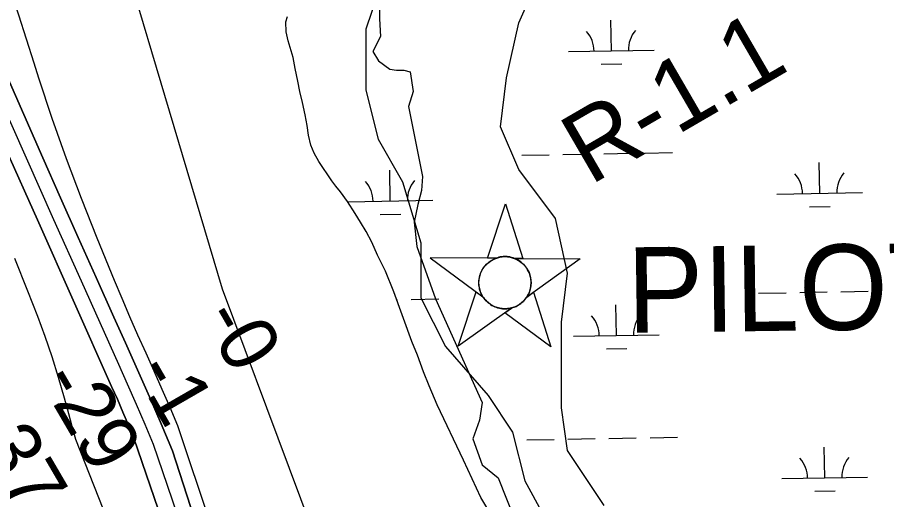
# Model space of a CAD drawing. Extents: x 3914892 to 3953151, y 242587 to 268572.
# Drawn here: x 3943744 to 3944760, y 249840 to 250403 of the extents above; entities that cross this region are included whole.
import ezdxf

# ---------------------------------------------------------------- set-up
doc = ezdxf.new("R2010")
doc.units = 0
for name, color, linetype in [('V-CHAN-NAID', 7, 'Continuous'), ('V-RIVR-EDGE', 7, 'Continuous'), ('V-RIVR-RANG', 7, 'Continuous'), ('V-RIVR-RANG-IDEN', 7, 'Continuous'), ('V-SITE-VEGE', 7, 'Continuous'), ('V-TOPO-DPTH', 7, 'Continuous'), ('V-TOPO-MINR', 7, 'Continuous'), ('V-TOPO-WATR', 7, 'Continuous'), ('V-WETL-SWMP', 7, 'Continuous')]:
    doc.layers.add(name, color=color, linetype=linetype)

msp = doc.modelspace()

# ---------------------------------------------------------------- linework, layer by layer
at = {"layer": 'V-CHAN-NAID'}
for points in [[(3944302.8, 250121.8), (3944293.3, 250121.8), (3944314.4, 250185.3), (3944334.6, 250121.5), (3944325, 250121.6), (3944323.4, 250122.2), (3944321.4, 250122.8), (3944319.3, 250123.3), (3944317.3, 250123.6), (3944316.1, 250123.7), (3944314.6, 250123.8), (3944312.9, 250123.8), (3944311.5, 250123.7), (3944309.6, 250123.5), (3944308.2, 250123.3), (3944306.4, 250122.9), (3944304.9, 250122.5), (3944303.9, 250122.1)], [(3944302.8, 250121.8), (3944226.4, 250122.3), (3944287.9, 250076.9), (3944286.8, 250078.8), (3944286, 250080.4), (3944285.2, 250082.4), (3944284.5, 250084.5), (3944284.1, 250085.8), (3944283.8, 250087.4), (3944283.5, 250088.9), (3944283.3, 250090.5), (3944283.2, 250092.2), (3944283.2, 250093.8), (3944283.3, 250095.8), (3944283.5, 250097.5), (3944283.9, 250099.7), (3944284.4, 250101.6), (3944285, 250103.5), (3944285.6, 250105.2), (3944286.3, 250106.7), (3944287.2, 250108.3), (3944288.2, 250110), (3944289.3, 250111.5), (3944290.3, 250112.8), (3944291.3, 250113.9), (3944292.6, 250115.2), (3944293.6, 250116.2), (3944295.3, 250117.6), (3944296.5, 250118.5), (3944298.2, 250119.5), (3944300, 250120.5), (3944301.4, 250121.2)], [(3944325, 250121.6), (3944401.5, 250121.1), (3944339.3, 250076.5), (3944340.2, 250078), (3944341.2, 250079.9), (3944341.9, 250081.5), (3944342.7, 250083.4), (3944343.2, 250085.2), (3944343.6, 250086.8), (3944344, 250088.8), (3944344.1, 250090.4), (3944344.3, 250092.6), (3944344.2, 250094.7), (3944344.1, 250096.9), (3944343.8, 250098.7), (3944343.3, 250100.9), (3944342.7, 250103), (3944341.9, 250105), (3944341.3, 250106.5), (3944340.2, 250108.4), (3944339.2, 250110.1), (3944338, 250111.8), (3944336.7, 250113.3), (3944335.4, 250114.7), (3944333.8, 250116.2), (3944332.1, 250117.7), (3944330.4, 250118.8), (3944328.5, 250120), (3944327, 250120.7)], [(3944321.3, 250063.6), (3944259.1, 250019.1), (3944280.2, 250082.6), (3944287.9, 250076.9), (3944288.6, 250075.9), (3944289.9, 250074.1), (3944291.2, 250072.7), (3944292.6, 250071.2), (3944294, 250069.9), (3944295.5, 250068.8), (3944296.9, 250067.8), (3944298.5, 250066.7), (3944300.3, 250065.8), (3944302, 250065), (3944303.5, 250064.5), (3944305.1, 250063.9), (3944307.3, 250063.4), (3944308.9, 250063.1), (3944310.9, 250062.8), (3944312.4, 250062.7), (3944314.3, 250062.7), (3944316, 250062.8), (3944317.7, 250062.9), (3944319.6, 250063.3)], [(3944339.3, 250076.5), (3944347.1, 250082.1), (3944367.3, 250018.3), (3944313.5, 250058.1), (3944321.3, 250063.6), (3944322.9, 250064.1), (3944324.6, 250064.7), (3944326.7, 250065.6), (3944328.5, 250066.5), (3944330.3, 250067.6), (3944332.1, 250068.8), (3944333.6, 250070), (3944334.9, 250071.2), (3944336.3, 250072.6), (3944337.5, 250074), (3944338.6, 250075.5)]]:
    msp.add_lwpolyline(points, close=True, dxfattribs=at)
msp.add_circle((3944313.7, 250093.2), 30.5, dxfattribs=at)
at = {"layer": 'V-RIVR-EDGE'}
msp.add_lwpolyline([(3944167.1, 250418.2), (3944167.1, 250401.8), (3944168.2, 250381.1), (3944159.5, 250363.6), (3944166, 250352.7), (3944179.1, 250342.9), (3944186.8, 250341.8), (3944195.5, 250341.8), (3944203.1, 250339.6), (3944206.4, 250316.7), (3944200.9, 250299.3), (3944217.3, 250217.4), (3944216.2, 250201.1), (3944211.8, 250184.7), (3944207.5, 250164), (3944210.8, 250135.6), (3944232.6, 250074.5), (3944287.1, 249953.4), (3944283.8, 249932.7), (3944276.2, 249910.9), (3944287.1, 249880.3), (3944305.7, 249865.1), (3944325.3, 249816)], dxfattribs=at)
at = {"layer": 'V-SITE-VEGE'}
for points in [[(3944429.7, 249832.9), (3944386.9, 249897.2), (3944379.7, 249947.1), (3944379.7, 250047.1), (3944386.9, 250104.2), (3944372.6, 250168.4), (3944329.8, 250225.5), (3944308.3, 250275.5), (3944315.5, 250332.6), (3944329.8, 250396.9), (3944358.3, 250461.1)], [(3944165.6, 250432.5), (3944151.3, 250389.7), (3944151.3, 250361.2), (3944151.3, 250318.3), (3944165.6, 250261.2), (3944194.1, 250211.3), (3944215.5, 250139.9), (3944215.5, 250075.6), (3944244.1, 250018.5), (3944294.1, 249961.4), (3944322.6, 249918.6), (3944336.9, 249861.5), (3944379.7, 249782.9)]]:
    msp.add_lwpolyline(points, dxfattribs=at)
at = {"layer": 'V-TOPO-DPTH'}
for points in [[(3944620.8, 248476), (3944296.7, 249247.2), (3943983.6, 250085.5), (3943808.9, 250673.8), (3943732.9, 250836.2), (3943663.5, 251001.9), (3943573.7, 251236.8), (3943554.7, 251287.8), (3943536.4, 251339), (3943519.1, 251390.6), (3943502.4, 251442.4), (3943485.5, 251496.3), (3943477.2, 251521.1), (3943468.2, 251545.7), (3943458.2, 251569.8), (3943447.5, 251593.7), (3943436.2, 251617.3), (3943424.7, 251640.8), (3943412.9, 251664.2), (3943401, 251687.5), (3943105.5, 252257.6)], [(3944118.2, 249216.8), (3943880.1, 249911.6), (3943873.7, 249926.8), (3943867.3, 249941.9), (3943860.8, 249957), (3943854.1, 249972), (3943767.3, 250166.8), (3943730.5, 250249.3), (3943693.6, 250331.8), (3943656.6, 250414.3), (3943619.6, 250496.7), (3943563.7, 250621.1), (3943554.6, 250641.4), (3943545.7, 250661.7), (3943536.9, 250682), (3943298.2, 251380.4), (3943287.2, 251406.6), (3943276.1, 251432.8), (3943264.8, 251458.9), (3943253.4, 251485), (3943092.2, 251970.5)], [(3943092.2, 251970.5), (3943253.4, 251485), (3943264.8, 251458.9), (3943276.1, 251432.8), (3943287.2, 251406.6), (3943298.2, 251380.4), (3943536.9, 250682), (3943545.7, 250661.7), (3943554.6, 250641.4), (3943563.7, 250621.1), (3943619.6, 250496.7), (3943656.6, 250414.3), (3943693.6, 250331.8), (3943730.5, 250249.3), (3943767.3, 250166.8), (3943854.1, 249972), (3943860.8, 249957), (3943867.3, 249941.9), (3943873.7, 249926.8), (3943880.1, 249911.6), (3944118.2, 249216.8)], [(3943581.5, 250676.8), (3943773.8, 250239.1), (3943794.4, 250192.5), (3943815.1, 250145.9), (3943835.9, 250099.4), (3943856.7, 250052.9), (3943870.3, 250022.8), (3943884.3, 249991.4), (3943898.2, 249959.9), (3943911.8, 249928.3), (3943925.3, 249896.6), (3944120, 249294.3)], [(3943581.5, 250676.8), (3943773.8, 250239.1), (3943794.4, 250192.5), (3943815.1, 250145.9), (3943835.9, 250099.4), (3943856.7, 250052.9), (3943870.3, 250022.8), (3943884.3, 249991.4), (3943898.2, 249959.9), (3943911.8, 249928.3), (3943925.3, 249896.6), (3944120, 249294.3)], [(3944107.3, 249161.8), (3943812.4, 249910), (3943808, 249925), (3943803.9, 249940.1), (3943799, 249958.4), (3943792.1, 249982.6), (3943784.7, 250006.6), (3943776.4, 250030.3), (3943767.7, 250053.8), (3943756, 250083.5), (3943740.8, 250121.7)], [(3944107.3, 249161.8), (3943812.4, 249910), (3943808, 249925), (3943803.9, 249940.1), (3943799, 249958.4), (3943792.1, 249982.6), (3943784.7, 250006.6), (3943776.4, 250030.3), (3943767.7, 250053.8), (3943756, 250083.5), (3943740.8, 250121.7)]]:
    msp.add_lwpolyline(points, dxfattribs=at)
at = {"layer": 'V-TOPO-MINR'}
for points in [[(3944118.2, 249216.8), (3943880.1, 249911.6), (3943873.7, 249926.8), (3943867.3, 249941.9), (3943860.8, 249957), (3943854.1, 249972), (3943767.3, 250166.8), (3943730.5, 250249.3), (3943693.6, 250331.8), (3943656.6, 250414.3), (3943619.6, 250496.7), (3943563.7, 250621.1), (3943554.6, 250641.4), (3943545.7, 250661.7), (3943536.9, 250682), (3943298.2, 251380.4), (3943287.2, 251406.6), (3943276.1, 251432.8), (3943264.8, 251458.9), (3943253.4, 251485), (3943092.2, 251970.5)], [(3944145.9, 249192), (3943903, 249904), (3943893.1, 249927.5), (3943883, 249951), (3943872.8, 249974.5), (3943862.4, 249997.8), (3943818.8, 250095), (3943786.6, 250166.9), (3943754.5, 250238.8), (3943722.4, 250310.8), (3943690.3, 250382.7), (3943572.2, 250648.2), (3943567.1, 250659.7), (3943562.1, 250671.3), (3943557.2, 250682.9), (3943313.6, 251401), (3943304.7, 251422.7), (3943149, 251911.8)], [(3944120, 249294.3), (3943925.3, 249896.6), (3943911.8, 249928.3), (3943898.2, 249959.9), (3943884.3, 249991.4), (3943870.3, 250022.8), (3943856.7, 250052.9), (3943835.9, 250099.4), (3943815.1, 250145.9), (3943794.4, 250192.5), (3943773.8, 250239.1), (3943581.5, 250676.8)], [(3944165.3, 249227.1), (3943931.5, 249926), (3943922.4, 249947.3), (3943913.2, 249968.5), (3943903.8, 249989.7), (3943894.3, 250010.9), (3943884.9, 250032.1), (3943875.5, 250053.3), (3943866.4, 250074.6), (3943857.5, 250096), (3943837.2, 250145.2), (3943818.9, 250191.5), (3943801.3, 250238), (3943784.8, 250285), (3943769.2, 250332.2), (3943763.6, 250349.9), (3943745.5, 250406.1), (3943727, 250462.2)], [(3944107.3, 249161.8), (3943812.4, 249910), (3943808, 249925), (3943803.9, 249940.1), (3943799, 249958.4), (3943792.1, 249982.6), (3943784.7, 250006.6), (3943776.4, 250030.3), (3943767.7, 250053.8), (3943756, 250083.5), (3943740.8, 250121.7)]]:
    msp.add_lwpolyline(points, dxfattribs=at)
at = {"layer": 'V-TOPO-WATR'}
msp.add_lwpolyline([(3944620.8, 248476), (3944296.7, 249247.2), (3943983.6, 250085.5), (3943808.9, 250673.8), (3943732.9, 250836.2), (3943663.5, 251001.9), (3943573.7, 251236.8), (3943554.7, 251287.8), (3943536.4, 251339), (3943519.1, 251390.6), (3943502.4, 251442.4), (3943485.5, 251496.3), (3943477.2, 251521.1), (3943468.2, 251545.7), (3943458.2, 251569.8), (3943447.5, 251593.7), (3943436.2, 251617.3), (3943424.7, 251640.8), (3943412.9, 251664.2), (3943401, 251687.5), (3943105.5, 252257.6)], dxfattribs=at)
at = {"layer": 'V-WETL-SWMP'}
for p, q in [((3944057.7, 250398.2), (3944059.6, 250404.3)), ((3944438, 250364.2), (3944437.3, 250400.1)), ((3944058.2, 250386.6), (3944057.7, 250398.2)), ((3944060.5, 250376.1), (3944058.2, 250386.6)), ((3944063.9, 250364.4), (3944060.5, 250376.1)), ((3944066.3, 250356.3), (3944063.9, 250364.4)), ((3944388, 250363.3), (3944488, 250365)), ((3944068.4, 250343.7), (3944066.3, 250356.3)), ((3944426.3, 250348.5), (3944450.3, 250348.9)), ((3944071.5, 250328.9), (3944068.4, 250343.7)), ((3944074.1, 250316.9), (3944071.5, 250328.9)), ((3944077.2, 250303.9), (3944074.1, 250316.9)), ((3944080.1, 250289.5), (3944077.2, 250303.9)), ((3944082.4, 250277.1), (3944080.1, 250289.5)), ((3944084.2, 250265.7), (3944082.4, 250277.1)), ((3944086.8, 250254.2), (3944084.2, 250265.7)), ((3944090.7, 250244.5), (3944086.8, 250254.2)), ((3944096.4, 250234.8), (3944090.7, 250244.5)), ((3944333.3, 250242.2), (3944365.3, 250242.8)), ((3944381.3, 250243), (3944413.3, 250243.6)), ((3944429.3, 250243.9), (3944461.3, 250244.5)), ((3944477.3, 250244.8), (3944509.3, 250245.3)), ((3944111.4, 250212.5), (3944096.4, 250234.8)), ((3944681.5, 250197.7), (3944680.8, 250233.7)), ((3944179.6, 250188.7), (3944179, 250224.7)), ((3944116.1, 250206.1), (3944111.4, 250212.5)), ((3944121.4, 250199.6), (3944116.1, 250206.1)), ((3944129.8, 250188.3), (3944121.4, 250199.6)), ((3944631.5, 250196.8), (3944731.5, 250198.6)), ((3944138.7, 250174.1), (3944129.8, 250188.3)), ((3944130.1, 250187.8), (3944229.6, 250189.6)), ((3944669.7, 250182), (3944693.7, 250182.5)), ((3944145, 250163.9), (3944138.7, 250174.1)), ((3944167.9, 250173), (3944191.9, 250173.5)), ((3944151.4, 250153.2), (3944145, 250163.9)), ((3944158.2, 250140.5), (3944151.4, 250153.2)), ((3944164.9, 250125.5), (3944158.2, 250140.5)), ((3944174, 250106.9), (3944164.9, 250125.5)), ((3944183.7, 250082.7), (3944174, 250106.9)), ((3944204.8, 250024.6), (3944183.7, 250082.7)), ((3944610.1, 250080.9), (3944642.1, 250081.5)), ((3944658.1, 250081.8), (3944690.1, 250082.4)), ((3944706.1, 250082.7), (3944738.1, 250083.2)), ((3944187.1, 250073.4), (3944188.3, 250073.4)), ((3944204.3, 250073.7), (3944236.3, 250074.3)), ((3944443.9, 250031.5), (3944443.3, 250067.5)), ((3944211.4, 250008.7), (3944204.8, 250024.6)), ((3944393.9, 250030.6), (3944493.9, 250032.4)), ((3944432.2, 250015.9), (3944456.2, 250016.3)), ((3944218.4, 249989), (3944211.4, 250008.7)), ((3944225.2, 249972.5), (3944218.4, 249989)), ((3944234.6, 249950.5), (3944225.2, 249972.5)), ((3944265.4, 249885.7), (3944234.6, 249950.5)), ((3944435.2, 249911.3), (3944467.2, 249911.9)), ((3944483.2, 249912.1), (3944515.2, 249912.7)), ((3944339.2, 249909.6), (3944371.2, 249910.1)), ((3944387.2, 249910.4), (3944419.2, 249911)), ((3944687.4, 249865), (3944686.8, 249901)), ((3944285.4, 249842.3), (3944265.4, 249885.7)), ((3944637.4, 249864.2), (3944737.4, 249865.9)), ((3944300.3, 249817.5), (3944285.4, 249842.3)), ((3944675.7, 249849.4), (3944699.7, 249849.8))]:
    msp.add_line(p, q, dxfattribs=at)
for centre, start, end in [((3944382.7, 250363.6), 0.2532, 41.7968), ((3944493.2, 250365.6), 140.2532, 181.7968), ((3944626.2, 250197.2), 0.2532, 41.7968), ((3944736.7, 250199.1), 140.2532, 181.7968), ((3944124.4, 250188.2), 0.2532, 41.7968), ((3944234.9, 250190.2), 140.2532, 181.7968), ((3944388.7, 250031), 0.2532, 41.7968), ((3944499.2, 250033), 140.2532, 181.7968), ((3944632.2, 249864.5), 0.2532, 41.7968), ((3944742.6, 249866.5), 140.2532, 181.7968)]:
    msp.add_arc(centre, 35.2, start, end, dxfattribs=at)

# ---------------------------------------------------------------- texts
at = {"layer": 'V-CHAN-NAID'}
msp.add_text('PILOTTOWN RANGE A REAR', height=100, rotation=0.8041, dxfattribs=at).set_placement((3944457, 250034.5))
at = {"layer": 'V-RIVR-RANG'}
for s, rotation, p in [('-0', 299.9783, (3943958, 250052.5)), ('-1', 299.9783, (3943878.9, 249989.6)), ('-29', 300.2615, (3943769.2, 249978.8)), ('-37', 300.2615, (3943682.2, 249929.5))]:
    msp.add_text(s, height=67, rotation=rotation, dxfattribs=at).set_placement(p)
at = {"layer": 'V-RIVR-RANG-IDEN'}
msp.add_text('R-1.1', height=83, rotation=30.1239, dxfattribs=at).set_placement((3944413.2, 250206.5))

doc.saveas('drawing.dxf')
